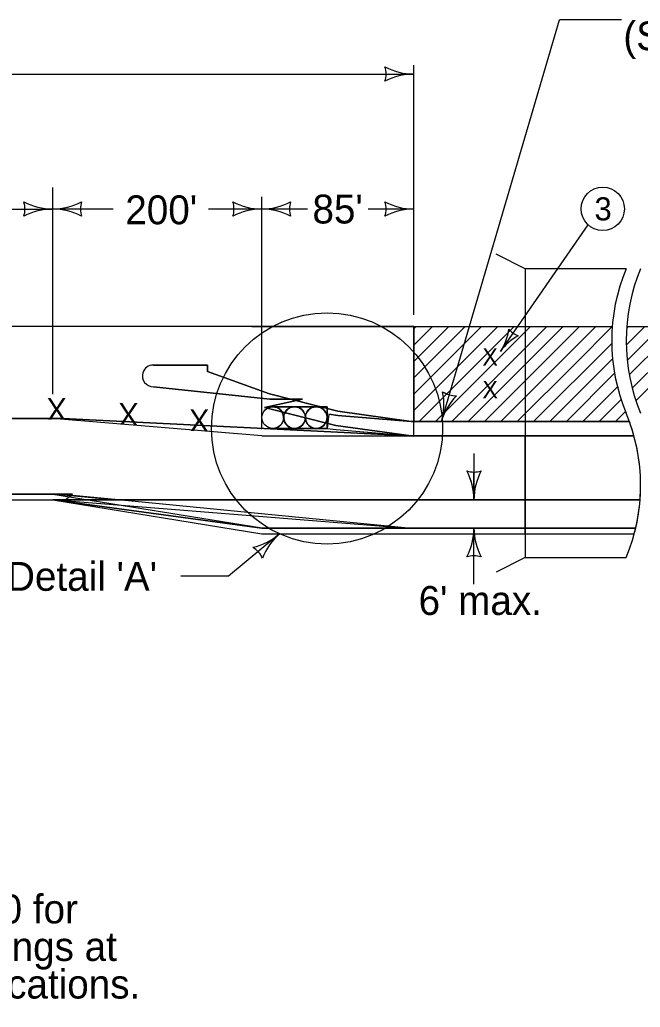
# Model space of a CAD drawing. Extents: x 10133 to 2270741, y 5363 to 1733450.
# Drawn here: x 26660 to 27089, y 8892 to 9575 of the extents above; entities that cross this region are included whole.
import ezdxf

# ---------------------------------------------------------------- set-up
doc = ezdxf.new("R2010")
doc.units = 0
for name, color, linetype in [('dsnNonPlotable', 7, 'Continuous'), ('dsnShtPlotShapeBatchPrint', 7, 'Continuous'), ('dsnStdBlockModified', 7, 'Continuous'), ('dsnStdBorder', 7, 'Continuous'), ('Level 12', 7, 'Continuous'), ('Level 2', 7, 'Continuous')]:
    doc.layers.add(name, color=color, linetype=linetype)

# ---------------------------------------------------------------- blocks, each defined once
blk = doc.blocks.new('LT')
at = {"layer": 'dsnStdBorder'}
for centre, radius, start, end in [((-3.564, 0), 1.642, 342.26665, 17.73335), ((0, 4.25), 4.25, 241.92751, 270), ((0, -4.25), 4.25, 90, 118.07249)]:
    blk.add_arc(centre, radius, start, end, dxfattribs=at)

msp = doc.modelspace()

# ---------------------------------------------------------------- linework, layer by layer
at = {"layer": 'dsnNonPlotable'}
for p, q in [((27009.38, 9403.06), (26989.38, 9413.06)), ((26024.67, 9299.33), (26682.42, 9299.33)), ((26827.18, 9287.33), (26682.42, 9299.33)), ((26930.48, 9297.33), (27081.61, 9297.33)), ((26827.18, 9287.33), (26930.48, 9287.33)), ((27084.78, 9287.33), (26930.48, 9287.32)), ((26491.2, 9247.04), (26681.32, 9247.04)), ((26682.51, 9243.06), (26911.34, 9243.06)), ((26911.34, 9243.06), (27088.99, 9243.06)), ((26827.18, 9223.56), (27085.98, 9223.56)), ((27009.38, 9203.06), (26989.38, 9193.06))]:
    msp.add_line(p, q, dxfattribs=at)
for points in [[(27079.38, 9403.06), (27009.38, 9403.06), (27009.38, 9203.06), (27079.38, 9203.06)], [(26873.6, 9302.31), (26872.34, 9292.46), (26872.34, 9292.46)], [(26873.6, 9302.31), (26879.83, 9301.5), (26930.48, 9297.33)], [(26872.34, 9292.46), (26878.57, 9291.65), (26930.48, 9287.33)]]:
    msp.add_lwpolyline(points, dxfattribs=at)
for centre, start, end in [((27199.38, 9353.06), 157.38014, 202.61987), ((27209.38, 9353.06), 157.38014, 202.61987), ((26959.38, 9253.06), 337.38014, 22.61987)]:
    msp.add_arc(centre, 130, start, end, dxfattribs=at)
at = {"layer": 'dsnShtPlotShapeBatchPrint'}
msp.add_circle((27063.18, 9444.47), 15, dxfattribs=at)
at = {"layer": 'dsnStdBlockModified'}
for p, q in [((26834.83, 9307.47), (26872.34, 9307.47)), ((26872.34, 9307.47), (26872.34, 9292.46)), ((26872.34, 9292.46), (26834.83, 9292.46))]:
    msp.add_line(p, q, dxfattribs=at)
for centre in [(26834.83, 9299.96), (26834.83, 9299.96), (26849.83, 9299.96), (26849.83, 9299.96), (26864.84, 9299.96), (26864.84, 9299.96)]:
    msp.add_circle(centre, 7.5, dxfattribs=at)
at = {"layer": 'dsnStdBorder'}
for p, q in [((26932.44, 9363.06), (26932.44, 9297.33)), ((26932.44, 9316.25), (26979.25, 9363.06)), ((26932.44, 9304.94), (26990.57, 9363.06)), ((26932.44, 9361.5), (26934, 9363.06)), ((26932.44, 9350.19), (26945.31, 9363.06)), ((26932.44, 9338.88), (26956.63, 9363.06)), ((26932.44, 9327.56), (26967.94, 9363.06)), ((26936.15, 9297.33), (27001.88, 9363.06)), ((26947.46, 9297.33), (27013.19, 9363.06)), ((26958.77, 9297.33), (27024.51, 9363.06)), ((26970.09, 9297.33), (27035.82, 9363.06)), ((26981.4, 9297.33), (27047.14, 9363.06)), ((26992.71, 9297.33), (27058.45, 9363.06)), ((27043.21, 9359.1), (27047.18, 9363.06)), ((27043.99, 9337.29), (27069.76, 9363.06)), ((27079.41, 9350.08), (27092.39, 9363.06)), ((27079.66, 9361.64), (27081.08, 9363.06)), ((27080.09, 9339.45), (27103.7, 9363.06)), ((27081.52, 9329.56), (27115.02, 9363.06)), ((27083.57, 9320.3), (27126.33, 9363.06)), ((27086.17, 9311.59), (27137.64, 9363.06)), ((27015.34, 9297.33), (27069.39, 9351.38)), ((27004.03, 9297.33), (27043.99, 9337.29)), ((27026.66, 9297.33), (27069.97, 9340.64)), ((27037.97, 9297.33), (27071.32, 9330.68)), ((27049.28, 9297.33), (27073.3, 9321.35)), ((27060.6, 9297.33), (27075.84, 9312.57)), ((27071.91, 9297.33), (27078.87, 9304.29)), ((26827.18, 9223.56), (26681.32, 9247.04))]:
    msp.add_line(p, q, dxfattribs=at)
for centre in [(26834.83, 9299.96), (26849.83, 9299.96), (26864.84, 9299.96)]:
    msp.add_circle(centre, 7.5, dxfattribs=at)
at = {"layer": 'Level 12'}
for p, q in [((26951.53, 9297.33), (27033.29, 9575.37)), ((27076.13, 9575.37), (27033.29, 9575.37)), ((26932.44, 9371.06), (26932.44, 9543.82)), ((26511.52, 9537.77), (26932.44, 9537.77)), ((26682.51, 9316.29), (26682.51, 9459.32)), ((26827.18, 9291.88), (26827.18, 9452.86)), ((26621.74, 9444.35), (26682.51, 9444.35)), ((26724.35, 9444.35), (26682.51, 9444.35)), ((26827.18, 9444.34), (26790.38, 9444.35)), ((26858.74, 9444.34), (26827.18, 9444.34)), ((26932.44, 9444.34), (26900.87, 9444.34)), ((26992.34, 9345.8), (27053.03, 9433.43)), ((26974.02, 9275.06), (26974.02, 9243.06)), ((26963.2, 9243.06), (26982.02, 9243.06)), ((26964.22, 9223.56), (26982.02, 9223.56)), ((26974.02, 9184.8), (26974.02, 9223.56)), ((26839.43, 9219.54), (26804.1, 9190.34)), ((26804.1, 9190.34), (26771.1, 9190.34))]:
    msp.add_line(p, q, dxfattribs=at)
msp.add_circle((26872.34, 9292.46), 80, dxfattribs=at)
for centre, radius, start, end in [((26896.81, 9537.77), 16.42, 342.26665, 17.73335), ((26932.44, 9580.27), 42.5, 241.92751, 270), ((26932.44, 9495.27), 42.5, 90, 118.07249), ((26646.88, 9444.35), 16.42, 342.26665, 17.73335), ((26682.51, 9486.85), 42.5, 241.92751, 270), ((26682.51, 9486.85), 42.5, 270, 298.07249), ((26718.15, 9444.35), 16.42, 162.26665, 197.73335), ((26791.54, 9444.34), 16.42, 342.26665, 17.73335), ((26827.18, 9486.84), 42.5, 241.92751, 270), ((26827.18, 9486.84), 42.5, 270, 298.07249), ((26862.81, 9444.34), 16.42, 162.26665, 197.73335), ((26896.81, 9444.34), 16.42, 342.26665, 17.73335), ((26932.44, 9486.84), 42.5, 241.92751, 270), ((26682.51, 9401.85), 42.5, 90, 118.07249), ((26682.51, 9401.85), 42.5, 61.92751, 90), ((26827.18, 9401.84), 42.5, 90, 118.07249), ((26827.18, 9401.84), 42.5, 61.92751, 90), ((26932.44, 9401.84), 42.5, 90, 118.07249), ((26910.75, 9309.32), 42.5, 343.61306, 11.68555), ((26961.58, 9331.51), 16.42, 235.87971, 271.34641), ((26992.3, 9285.34), 42.5, 135.54057, 163.61306), ((26974.02, 9278.7), 16.42, 252.26665, 287.73335), ((26931.52, 9243.06), 42.5, 360, 28.07249), ((27016.52, 9243.06), 42.5, 151.92751, 180), ((26931.52, 9223.56), 42.5, 331.92751, 360), ((27016.52, 9223.56), 42.5, 180, 208.07249), ((26811.53, 9251.6), 42.5, 282.97403, 311.04652), ((26867.34, 9187.49), 42.5, 131.04652, 159.11901), ((26812.56, 9196.14), 16.42, 23.31317, 58.77987), ((26974.02, 9187.92), 16.42, 72.26665, 107.73335)]:
    msp.add_arc(centre, radius, start, end, dxfattribs=at)
at = {"layer": 'Level 2'}
for p, q in [((26820.3, 9363.06), (25605.94, 9363.06)), ((26820.3, 9363.06), (27069.76, 9363.06)), ((27079.76, 9363.06), (27646.69, 9363.06)), ((26932.44, 9338.88), (26932.44, 9350.19)), ((26789.6, 9331.98), (26789.6, 9336.34)), ((26832.69, 9312.82), (26752.21, 9321.34)), ((26752.21, 9321.34), (26832.69, 9312.82)), ((26847.7, 9312.82), (26832.95, 9312.82)), ((26832.95, 9312.82), (26847.7, 9312.82)), ((26855.33, 9312.82), (26847.95, 9312.82)), ((26847.95, 9312.82), (26855.33, 9312.82)), ((26932.44, 9304.94), (26932.44, 9316.25)), ((26849.45, 9307.48), (26834.84, 9307.48)), ((26864.46, 9307.48), (26849.45, 9307.48)), ((26872.35, 9307.48), (26864.46, 9307.48)), ((26872.35, 9300.37), (26872.35, 9307.48)), ((26932.44, 9297.33), (26932.44, 9304.94)), ((26689.43, 9299.33), (26127.98, 9299.33)), ((26656.64, 9299.33), (26689.43, 9299.33)), ((26689.43, 9299.33), (26930.48, 9287.33)), ((26930.48, 9287.33), (26689.43, 9299.33)), ((26873.6, 9302.31), (26872.34, 9292.46)), ((26872.35, 9292.48), (26872.35, 9299.98)), ((27081.61, 9297.33), (26930.48, 9297.33)), ((26932.44, 9287.23), (26932.44, 9297.33)), ((26835.23, 9292.48), (26849.8, 9292.48)), ((26850.24, 9292.48), (26865.24, 9292.48)), ((26865.24, 9292.48), (26872.35, 9292.48)), ((26930.48, 9287.32), (27084.78, 9287.33)), ((27009.38, 9287.33), (26930.48, 9287.33)), ((26930.48, 9287.33), (26932.44, 9287.23)), ((27084.78, 9287.33), (27009.38, 9287.33)), ((27009.38, 9287.33), (27009.38, 9243.06)), ((27009.38, 9243.06), (27009.38, 9287.33)), ((26974.02, 9243.06), (26974.02, 9262.28)), ((26141.22, 9243.06), (26691.24, 9243.06)), ((26696.29, 9247.06), (26144.15, 9247.06)), ((26682.59, 9243.06), (26682.51, 9243.06)), ((26682.51, 9243.06), (26827.18, 9219.56)), ((26682.51, 9243.06), (26827.18, 9219.56)), ((26827.18, 9223.56), (26682.59, 9243.06)), ((26911.34, 9243.06), (26682.59, 9243.06)), ((26682.59, 9243.06), (26827.18, 9223.56)), ((26685.34, 9247.04), (26726.5, 9243.06)), ((26727.85, 9243.06), (26686.53, 9243.06)), ((26686.53, 9243.06), (26692.84, 9242.45)), ((26727.85, 9243.06), (26686.74, 9247.06)), ((26691.24, 9243.06), (26696.29, 9247.06)), ((26692.84, 9242.45), (26928.4, 9223.56)), ((26726.5, 9243.06), (26727.85, 9243.06)), ((26928.4, 9223.56), (26727.85, 9243.06)), ((26727.85, 9243.06), (26911.34, 9243.06)), ((27088.99, 9243.06), (27009.38, 9243.06)), ((27009.38, 9243.06), (27009.38, 9223.56)), ((27009.38, 9243.06), (27088.99, 9243.06)), ((27009.38, 9223.56), (27009.38, 9243.06)), ((26974.02, 9223.56), (26827.18, 9223.56)), ((26827.18, 9223.56), (26964.22, 9223.56)), ((26928.41, 9223.56), (27085.98, 9223.56)), ((26964.22, 9223.56), (26974.02, 9223.56)), ((26982.02, 9223.56), (26974.02, 9223.56)), ((26974.02, 9223.56), (26982.02, 9223.56)), ((27009.38, 9223.56), (26982.02, 9223.56)), ((26982.02, 9223.56), (27009.38, 9223.56)), ((27009.38, 9223.56), (27085.98, 9223.56)), ((27009.38, 9219.56), (27009.38, 9223.56)), ((27009.38, 9223.56), (27009.38, 9219.56)), ((27059.64, 9223.56), (27085.98, 9223.56)), ((26827.18, 9219.56), (27084.99, 9219.56)), ((26827.18, 9219.56), (26973.84, 9219.56)), ((26974.21, 9219.56), (27009.38, 9219.56)), ((27058.64, 9219.56), (27084.99, 9219.56))]:
    msp.add_line(p, q, dxfattribs=at)
for points in [[(26932.44, 9363.06), (26892.12, 9363.06), (26820.3, 9363.06)], [(26932.44, 9350.19), (26932.44, 9361.5), (26932.44, 9363.06)], [(26932.44, 9316.25), (26932.44, 9327.56), (26932.44, 9338.88)], [(26752.09, 9336.34), (26752.09, 9336.34), (26782.08, 9336.34), (26782.11, 9336.34), (26789.6, 9336.34)], [(26789.6, 9336.34), (26782.08, 9336.34), (26752.09, 9336.34)], [(26789.6, 9336.34), (26789.6, 9331.98), (26789.6, 9331.98)], [(26789.6, 9331.98), (26832.45, 9316.38), (26879.73, 9304.46), (26930.48, 9297.33), (26932.44, 9297.33)], [(26932.44, 9297.33), (26930.48, 9297.33), (26879.73, 9304.46), (26832.45, 9316.38), (26789.6, 9331.98)], [(26930.48, 9287.33), (26878.55, 9294.58), (26829.03, 9306.98), (26855.33, 9312.82)], [(26855.33, 9312.82), (26829.03, 9306.98), (26878.55, 9294.58), (26930.48, 9287.33)], [(26849.45, 9307.47), (26849.45, 9307.48)], [(26849.45, 9307.48), (26849.45, 9307.47)], [(26864.46, 9307.47), (26864.46, 9307.48)], [(26864.46, 9307.48), (26864.46, 9307.47)], [(26842.33, 9300.37), (26842.35, 9300.37)], [(26857.34, 9300.37), (26857.36, 9300.37)], [(26872.34, 9300.37), (26872.35, 9300.37)], [(26930.48, 9297.33), (26879.83, 9301.5), (26873.6, 9302.31)], [(26835.23, 9292.49), (26835.23, 9292.48)], [(26850.24, 9292.49), (26850.24, 9292.48)], [(26865.24, 9292.49), (26865.24, 9292.48)], [(26865.24, 9292.48), (26865.24, 9292.49)], [(26872.34, 9292.46), (26878.57, 9291.65), (26930.13, 9287.36), (26930.48, 9287.33)], [(26930.48, 9287.33), (26930.48, 9287.32)], [(25968.2, 9247.04), (26687.28, 9247.04), (26685.34, 9247.04)], [(26649.72, 9243.06), (26686.53, 9243.06), (26727.85, 9243.06)], [(26686.74, 9247.06), (26685.77, 9247.06), (26654.56, 9247.06)], [(27009.38, 9243.06), (26982.02, 9243.06), (26974.02, 9243.06), (26963.2, 9243.06), (26911.34, 9243.06)], [(26911.34, 9243.06), (26963.2, 9243.06), (26974.02, 9243.06)], [(26974.02, 9243.06), (26982.02, 9243.06), (27009.38, 9243.06)], [(27085.98, 9223.56), (27059.64, 9223.56), (27009.38, 9223.56)], [(27009.38, 9219.56), (27058.64, 9219.56), (27084.99, 9219.56)]]:
    msp.add_lwpolyline(points, dxfattribs=at)
for centre, radius, start, end in [((26752.09, 9328.84), 7.5, 163.04978, 270.9263), ((26752.09, 9328.84), 7.5, 163.04978, 270.9263), ((26752.09, 9328.84), 7.5, 90, 163.05255), ((26752.09, 9328.84), 7.5, 90, 163.05255), ((26832.82, 9320.32), 7.5, 268.97742, 271.02258), ((26832.82, 9320.32), 7.5, 268.97742, 271.02258), ((26847.82, 9320.32), 7.5, 269.06509, 270.93491), ((26847.82, 9320.32), 7.5, 269.06509, 270.93491), ((26834.84, 9299.98), 7.5, 3.00007, 92.99993), ((26834.84, 9299.98), 7.5, 2.99574, 90), ((26849.85, 9299.98), 7.5, 93.04482, 93), ((26849.85, 9299.98), 7.5, 93.04172, 177.01242), ((26849.85, 9299.98), 7.5, 2.99574, 92.9969), ((26864.85, 9299.98), 7.5, 93.00604, 182.99396), ((26864.85, 9299.98), 7.5, 92.9969, 177.01242), ((26864.84, 9299.96), 7.51, 3.1005, 92.8995), ((26864.85, 9299.98), 7.5, 2.99593, 92.9969), ((26834.82, 9300.02), 7.55, 273.14031, 356.68109), ((26834.82, 9300.02), 7.55, 317.82762, 356.66631), ((26849.85, 9299.98), 7.5, 183.01314, 269.67748), ((26849.82, 9300.02), 7.55, 273.14439, 356.67701), ((26849.82, 9300.02), 7.55, 318.90204, 356.5996), ((26864.85, 9299.98), 7.5, 182.99578, 273.00422), ((26864.85, 9299.98), 7.5, 183.08128, 273.00246), ((26864.85, 9299.98), 7.5, 272.99981, 3.00019), ((26864.85, 9299.98), 7.5, 273.00246, 0), ((26959.38, 9253.06), 130, 15.28231, 19.90723), ((26834.84, 9299.98), 7.5, 273.00246, 317.97075), ((26849.85, 9299.98), 7.5, 272.99983, 319.05414), ((26959.38, 9253.06), 130, 355.58827, 15.28231), ((26974.02, 9278.7), 16.42, 252.26665, 270), ((26931.52, 9243.06), 42.5, 0.0176, 28.07249), ((27016.52, 9243.06), 42.5, 179.9824, 180), ((26959.38, 9253.06), 130, 346.88165, 355.58827), ((26931.52, 9223.56), 42.5, 354.59945, 360), ((26931.52, 9223.56), 42.5, 359.9824, 360), ((27016.52, 9223.56), 42.5, 180.0176, 185.40055), ((26959.38, 9253.06), 130, 345.06444, 346.88165)]:
    msp.add_arc(centre, radius, start, end, dxfattribs=at)

# ---------------------------------------------------------------- block references
at = {"layer": 'Level 12', "xscale": 7.999600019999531, "yscale": 7.999200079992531, "rotation": -124.70293665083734}
msp.add_blockref('LT', (26992.34, 9345.8), dxfattribs=at)

# ---------------------------------------------------------------- texts
at = {"layer": 'dsnShtPlotShapeBatchPrint'}
msp.add_text('3', height=16, dxfattribs=at).set_placement((27057.47, 9436.47))
at = {"layer": 'dsnStdBorder'}
for s, height, p in [('X', 12, (26979.9, 9335.98)), ('X', 12, (26979.9, 9313.34)), ('Refer to TC-420 for', 20, (26469.56, 8949.87)), ('remainder of signings at', 20, (26441.5, 8923.87)), ('ramps and their locations.', 20, (26436.89, 8897.87))]:
    msp.add_text(s, height=height, dxfattribs=at).set_placement(p)
for p in [(26691.94, 9313.57), (26741.69, 9310.04), (26790.63, 9305.81)]:
    msp.add_text('X', height=15, rotation=180, dxfattribs=at).set_placement(p)
at = {"layer": 'Level 12'}
for s, p in [('(See Typical 8210)', (27077.41, 9554.22)), ("200'", (26732.75, 9433.79)), ("85'", (26862.26, 9434.34)), ("See Detail 'A'", (26595.87, 9180.09)), ("6' max.", (26935.71, 9163.39))]:
    msp.add_text(s, height=20, dxfattribs=at).set_placement(p)

doc.saveas('drawing.dxf')
